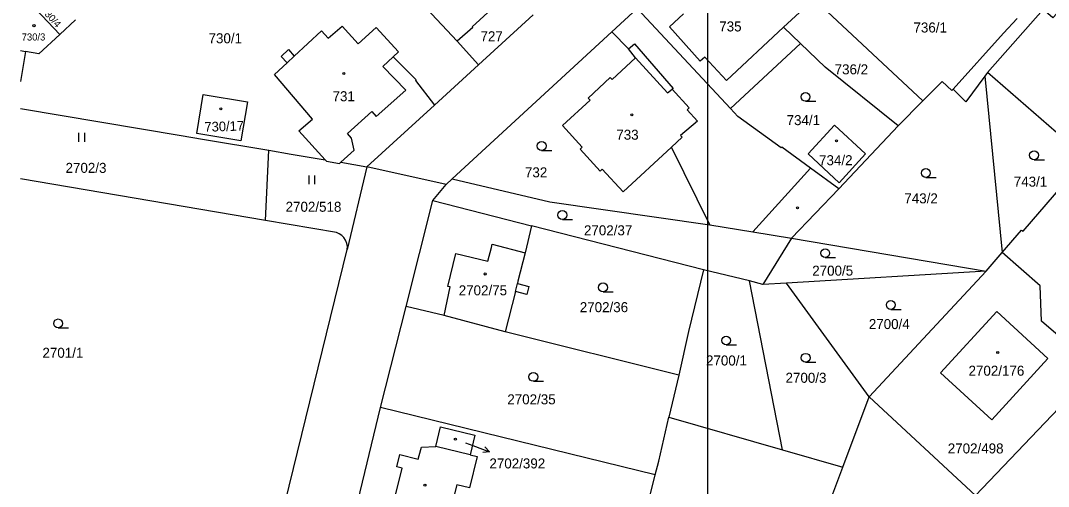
# Model space of a CAD drawing. Extents: x -496682 to -495907, y -1088575 to -1088018.
# Drawn here: x -496674.2 to -496499.5, y -1088360.6 to -1088281.4 of the extents above; entities that cross this region are included whole.
import ezdxf

# ---------------------------------------------------------------- set-up
doc = ezdxf.new("R2010")
doc.units = 0
for name, color, linetype in [('Hranice parcel', 7, 'Continuous'), ('Parcelní čísla', 7, 'Continuous'), ('Pop  PČ popisy', 7, 'Continuous'), ('Vnitřní kresba', 7, 'Continuous'), ('Vrstva 63', 7, 'Continuous'), ('Značky budov', 7, 'Continuous'), ('Značky kultur', 7, 'Continuous')]:
    doc.layers.add(name, color=color, linetype=linetype)

msp = doc.modelspace()

# ---------------------------------------------------------------- linework, layer by layer
at = {"layer": 'Hranice parcel'}
for p, q in [((-496548.9, -1088268.78), (-496520.79, -1088295.03)), ((-496667.54, -1088283.8), (-496671.59, -1088279.46)), ((-496569.37, -1088279.38), (-496573.69, -1088283.35)), ((-496553.5, -1088296.38), (-496569.37, -1088279.38)), ((-496664.84, -1088281.29), (-496667.54, -1088283.8)), ((-496596.36, -1088288.95), (-496587.04, -1088280.45)), ((-496573.69, -1088283.35), (-496600.82, -1088308.29)), ((-496674.2, -1088286.47), (-496673.36, -1088286.64)), ((-496673.36, -1088286.64), (-496674.2, -1088291.77)), ((-496599.99, -1088284.92), (-496596.36, -1088288.95)), ((-496541.63, -1088285.29), (-496553.5, -1088296.38)), ((-496603.81, -1088295.77), (-496596.36, -1088288.95)), ((-496509.82, -1088290.25), (-496510.27, -1088290.86)), ((-496510.27, -1088290.86), (-496507.31, -1088320.82)), ((-496493.08, -1088304.83), (-496509.82, -1088290.25)), ((-496524.98, -1088299.32), (-496520.79, -1088295.03)), ((-496615.31, -1088306.29), (-496603.81, -1088295.77)), ((-496535.11, -1088310.03), (-496524.98, -1088299.32)), ((-496632.58, -1088315.39), (-496631.97, -1088303.45)), ((-496615.31, -1088306.29), (-496618.66, -1088320.33)), ((-496601.85, -1088309.24), (-496615.31, -1088306.29)), ((-496632.58, -1088315.39), (-496674.2, -1088308.3)), ((-496604.09, -1088312.01), (-496601.85, -1088309.24)), ((-496600.82, -1088308.29), (-496601.85, -1088309.24)), ((-496543.15, -1088318.39), (-496535.11, -1088310.03)), ((-496608.66, -1088330.02), (-496604.09, -1088312.01)), ((-496604.09, -1088312.01), (-496587.31, -1088316.31)), ((-496620.51, -1088317.45), (-496632.58, -1088315.39)), ((-496558.12, -1088323.79), (-496587.31, -1088316.31)), ((-496543.15, -1088318.39), (-496547.99, -1088326.24)), ((-496543.15, -1088318.39), (-496510.05, -1088324)), ((-496629.19, -1088363.28), (-496618.66, -1088320.33)), ((-496510.05, -1088324), (-496507.31, -1088320.82)), ((-496550.3, -1088325.66), (-496558.12, -1088323.79)), ((-496510.05, -1088324), (-496543.99, -1088326.01)), ((-496529.95, -1088345.34), (-496510.05, -1088324)), ((-496544.65, -1088354.34), (-496550.3, -1088325.66)), ((-496547.99, -1088326.24), (-496550.3, -1088325.66)), ((-496543.99, -1088326.01), (-496547.99, -1088326.24)), ((-496529.95, -1088345.34), (-496543.99, -1088326.01)), ((-496613.01, -1088347.16), (-496608.66, -1088330.02)), ((-496562.31, -1088341.65), (-496591.79, -1088334.31)), ((-496562.31, -1088341.65), (-496563.97, -1088348.81)), ((-496534.41, -1088357.28), (-496529.95, -1088345.34)), ((-496511.87, -1088362.1), (-496529.95, -1088345.34)), ((-496617.24, -1088364.65), (-496613.01, -1088347.16)), ((-496566.3, -1088358.61), (-496613.01, -1088347.16)), ((-496563.97, -1088348.81), (-496544.65, -1088354.34)), ((-496597.79, -1088355.21), (-496603.63, -1088353.81)), ((-496544.65, -1088354.34), (-496534.41, -1088357.28)), ((-496549.47, -1088397.55), (-496534.41, -1088357.28)), ((-496570.63, -1088376), (-496566.3, -1088358.61))]:
    msp.add_line(p, q, dxfattribs=at)
for points in [[(-496541.63, -1088285.29), (-496544.48, -1088282.55), (-496541.11, -1088279.41), (-496545.16, -1088275.06), (-496544.67, -1088274.27), (-496549.3, -1088269.14), (-496548.9, -1088268.78)], [(-496613.46, -1088270.55), (-496609.56, -1088274.67), (-496599.99, -1088284.92)], [(-496471.64, -1088280.48), (-496481.44, -1088271.8), (-496490.1, -1088271.56), (-496498.71, -1088280.96), (-496500.38, -1088279.53), (-496509.82, -1088290.25)], [(-496590.86, -1088276.42), (-496597.43, -1088282.45), (-496597.33, -1088282.57), (-496599.99, -1088284.92)], [(-496515.68, -1088293.05), (-496507.09, -1088283.57), (-496504.76, -1088281.06)], [(-496622.44, -1088305.06), (-496626.89, -1088300.16), (-496624.57, -1088298.15), (-496631.04, -1088290.58), (-496628.89, -1088288.59), (-496629.91, -1088287.49), (-496628.67, -1088286.35), (-496627.66, -1088287.45), (-496623.04, -1088283.17), (-496621.92, -1088284.39), (-496619.54, -1088282.35), (-496616.81, -1088285.36), (-496613.73, -1088282.57), (-496609.93, -1088286.75), (-496610.83, -1088287.57), (-496606.92, -1088291.49), (-496607.06, -1088291.61), (-496603.81, -1088295.77)], [(-496667.54, -1088283.8), (-496671.07, -1088287.09), (-496673.36, -1088286.64)], [(-496557.01, -1088316.13), (-496563.54, -1088302.9), (-496571.78, -1088310.53), (-496575.32, -1088306.66), (-496575.68, -1088306.99), (-496579.09, -1088303.24), (-496578.73, -1088302.91), (-496582.06, -1088299.26), (-496577.39, -1088294.94), (-496577.72, -1088294.58), (-496573.95, -1088291.1), (-496573.62, -1088291.45), (-496569.64, -1088287.77), (-496570.83, -1088286.2), (-496573.69, -1088283.35)], [(-496524.98, -1088299.32), (-496537.43, -1088289.33), (-496541.63, -1088285.29)], [(-496520.79, -1088295.03), (-496517.54, -1088291.78), (-496515.9, -1088293.3), (-496515.68, -1088293.05)], [(-496510.27, -1088290.86), (-496513.48, -1088295.21), (-496515.68, -1088293.05)], [(-496636.73, -1088301.87), (-496644.24, -1088300.6), (-496643.15, -1088293.97), (-496635.64, -1088295.22), (-496636.73, -1088301.87)], [(-496674.2, -1088296.34), (-496646.9, -1088300.94), (-496643.26, -1088301.55), (-496631.97, -1088303.45)], [(-496535.11, -1088310.03), (-496539.93, -1088306.49), (-496544.78, -1088302.93), (-496544.87, -1088303.05), (-496552.24, -1088297.73), (-496553.5, -1088296.38)], [(-496535.04, -1088308.98), (-496540.33, -1088304.08), (-496535.81, -1088299.21), (-496530.53, -1088304.07), (-496535.04, -1088308.98)], [(-496631.97, -1088303.45), (-496628.18, -1088304.09), (-496622.44, -1088305.06)], [(-496622.44, -1088305.06), (-496622.2, -1088305.33), (-496619.97, -1088305.68), (-496619.76, -1088305.49), (-496615.31, -1088306.29)], [(-496507.31, -1088320.82), (-496504.02, -1088317), (-496503.76, -1088317.22), (-496493.08, -1088304.83)], [(-496600.82, -1088308.29), (-496584.23, -1088312.23), (-496557.01, -1088316.13)], [(-496587.31, -1088316.31), (-496588.44, -1088320.85), (-496589.65, -1088325.71), (-496589.74, -1088326.09), (-496587.78, -1088326.58), (-496588.11, -1088327.93), (-496590.08, -1088327.44), (-496591.79, -1088334.31)], [(-496557.01, -1088316.13), (-496549.73, -1088317.32), (-496543.15, -1088318.39)], [(-496618.66, -1088320.33), (-496618.64, -1088319.82), (-496618.71, -1088319.31), (-496618.89, -1088318.83), (-496618.96, -1088318.7), (-496619.24, -1088318.28), (-496619.61, -1088317.92), (-496620.04, -1088317.64), (-496620.51, -1088317.45)], [(-496495.35, -1088337), (-496500.62, -1088332.48), (-496500.87, -1088326.47), (-496507.31, -1088320.82)], [(-496558.12, -1088323.79), (-496560.67, -1088334.24), (-496562.31, -1088341.65)], [(-496591.79, -1088334.31), (-496602.19, -1088331.54), (-496608.66, -1088330.02)], [(-496508.23, -1088330.82), (-496517.83, -1088341.24), (-496509.1, -1088349.28), (-496499.58, -1088338.82), (-496508.23, -1088330.82)], [(-496495.35, -1088337), (-496495.31, -1088344.8), (-496511.87, -1088362.1)], [(-496566.3, -1088358.61), (-496565.71, -1088356.26), (-496563.97, -1088348.81)], [(-496603.63, -1088353.81), (-496602.83, -1088350.47), (-496597, -1088351.88), (-496597.79, -1088355.21)], [(-496611.47, -1088366.13), (-496609.31, -1088357.47), (-496610.23, -1088357.24), (-496609.71, -1088355.17), (-496606.59, -1088355.94), (-496606.43, -1088355.33), (-496606.05, -1088353.9), (-496603.63, -1088353.81)], [(-496597.79, -1088355.21), (-496596.58, -1088355.5), (-496597.86, -1088360.83), (-496600.06, -1088360.3), (-496602.12, -1088368.5)]]:
    msp.add_lwpolyline(points, dxfattribs=at)
at = {"layer": 'Pop  PČ popisy'}
for p, q in [((-496598.58, -1088353.17), (-496597.3, -1088353.64)), ((-496597.3, -1088353.64), (-496594.48, -1088354.67)), ((-496594.48, -1088354.67), (-496595.59, -1088354.79)), ((-496594.48, -1088354.67), (-496595.25, -1088353.85))]:
    msp.add_line(p, q, dxfattribs=at)
at = {"layer": 'Vnitřní kresba'}
for p, q in [((-496563.86, -1088282.47), (-496561.48, -1088280.26)), ((-496558.66, -1088288.31), (-496563.86, -1088282.47)), ((-496544.48, -1088282.55), (-496554.18, -1088291.59)), ((-496570.83, -1088286.2), (-496569.84, -1088285.35)), ((-496569.84, -1088285.35), (-496563.27, -1088292.94)), ((-496627.66, -1088287.45), (-496628.89, -1088288.59)), ((-496612.62, -1088289.19), (-496610.83, -1088287.57)), ((-496569.64, -1088287.77), (-496564.22, -1088293.68)), ((-496557.88, -1088287.62), (-496558.66, -1088288.31)), ((-496554.18, -1088291.59), (-496557.88, -1088287.62)), ((-496608.71, -1088293.21), (-496612.62, -1088289.19)), ((-496613.73, -1088297.7), (-496608.71, -1088293.21)), ((-496564.22, -1088293.68), (-496563.42, -1088293.06)), ((-496563.27, -1088292.94), (-496563.42, -1088293.06)), ((-496563.42, -1088293.06), (-496560.51, -1088296.25)), ((-496618.63, -1088300.61), (-496614.51, -1088296.84)), ((-496614.51, -1088296.84), (-496613.73, -1088297.7)), ((-496560.51, -1088296.25), (-496560.88, -1088296.59)), ((-496560.88, -1088296.59), (-496559.1, -1088298.52)), ((-496559.1, -1088298.52), (-496561.98, -1088300.95)), ((-496617.93, -1088301.38), (-496618.63, -1088300.61)), ((-496617.51, -1088303.44), (-496617.93, -1088301.38)), ((-496561.73, -1088301.22), (-496563.54, -1088302.9)), ((-496561.98, -1088300.95), (-496561.73, -1088301.22)), ((-496619.76, -1088305.49), (-496617.51, -1088303.44)), ((-496539.93, -1088306.49), (-496549.73, -1088317.32)), ((-496594.15, -1088319.98), (-496594.01, -1088319.42)), ((-496594.01, -1088319.42), (-496588.44, -1088320.85)), ((-496601.58, -1088326.57), (-496600.18, -1088320.97)), ((-496600.18, -1088320.97), (-496594.74, -1088322.29)), ((-496594.74, -1088322.29), (-496594.15, -1088319.98)), ((-496602.19, -1088331.54), (-496601.19, -1088326.65)), ((-496601.19, -1088326.65), (-496601.58, -1088326.57)), ((-496590.08, -1088327.44), (-496589.74, -1088326.09))]:
    msp.add_line(p, q, dxfattribs=at)
at = {"layer": 'Vrstva 63'}
msp.add_lwpolyline([(-496137.35, -1088164.24), (-496137.35, -1088461.24), (-496557.35, -1088461.24), (-496557.35, -1088164.24)], close=True, dxfattribs=at)
at = {"layer": 'Značky budov'}
for centre in [(-496671.92, -1088282.28), (-496619.24, -1088290.39), (-496640.16, -1088296.42), (-496570.29, -1088297.44), (-496535.47, -1088301.84), (-496542.11, -1088313.23), (-496595.2, -1088324.47), (-496508.08, -1088337.83), (-496600.28, -1088352.55), (-496605.45, -1088360.35)]:
    msp.add_circle(centre, 0.175, dxfattribs=at)
at = {"layer": 'Značky kultur'}
for p, q in [((-496540.75, -1088295.13), (-496539, -1088295.13)), ((-496664.27, -1088301.99), (-496664.27, -1088300.49)), ((-496663.27, -1088301.99), (-496663.27, -1088300.49)), ((-496585.61, -1088303.47), (-496583.86, -1088303.47)), ((-496501.9, -1088305.05), (-496500.15, -1088305.05)), ((-496625.15, -1088309.23), (-496625.15, -1088307.73)), ((-496624.15, -1088309.23), (-496624.15, -1088307.73)), ((-496520.3, -1088308.07), (-496518.55, -1088308.07)), ((-496582.09, -1088315.2), (-496580.34, -1088315.2)), ((-496537.4, -1088321.69), (-496535.65, -1088321.69)), ((-496575.18, -1088327.5), (-496573.43, -1088327.5)), ((-496526.26, -1088330.48), (-496524.51, -1088330.48)), ((-496667.82, -1088333.62), (-496666.07, -1088333.62)), ((-496554.25, -1088336.52), (-496552.5, -1088336.52)), ((-496540.73, -1088339.46), (-496538.98, -1088339.46)), ((-496587.02, -1088342.71), (-496585.27, -1088342.71))]:
    msp.add_line(p, q, dxfattribs=at)
for centre in [(-496540.75, -1088294.38), (-496585.61, -1088302.72), (-496501.9, -1088304.3), (-496520.3, -1088307.32), (-496582.09, -1088314.45), (-496537.4, -1088320.94), (-496575.18, -1088326.75), (-496526.26, -1088329.73), (-496667.82, -1088332.87), (-496554.25, -1088335.77), (-496540.73, -1088338.71), (-496587.02, -1088341.96)]:
    msp.add_circle(centre, 0.75, dxfattribs=at)

# ---------------------------------------------------------------- texts
at = {"layer": 'Parcelní čísla'}
for s, height, rotation, p in [('730/4', 1.2, 312, (-496670.79, -1088279.72)), ('730/17', 1.643, 2, (-496642.91, -1088300.32))]:
    msp.add_text(s, height=height, rotation=rotation, dxfattribs=at).set_placement(p)
for s, height, p in [('735', 1.7, (-496555.42, -1088283.26)), ('736/1', 1.7, (-496522.4, -1088283.44)), ('730/3', 1.2, (-496674.01, -1088284.8)), ('730/1', 1.7, (-496642.24, -1088285.27)), ('727', 1.7, (-496596.01, -1088284.93)), ('736/2', 1.7, (-496535.8, -1088290.55)), ('731', 1.7, (-496621.16, -1088295.12)), ('734/1', 1.7, (-496543.97, -1088299.18)), ('733', 1.7, (-496572.92, -1088301.66)), ('2702/3', 1.7, (-496666.55, -1088307.29)), ('734/2', 1.7, (-496538.45, -1088305.99)), ('732', 1.7, (-496588.45, -1088308.05)), ('743/1', 1.7, (-496505.35, -1088309.63)), ('743/2', 1.7, (-496523.95, -1088312.47)), ('2702/518', 1.7, (-496629.14, -1088313.9)), ('2702/37', 1.7, (-496578.42, -1088317.9)), ('2700/5', 1.7, (-496539.61, -1088324.76)), ('2702/75', 1.7, (-496599.71, -1088328.1)), ('2702/36', 1.7, (-496579.13, -1088330.96)), ('2700/4', 1.7, (-496529.99, -1088333.83)), ('2701/1', 1.7, (-496670.48, -1088338.71)), ('2700/1', 1.7, (-496557.67, -1088340.02)), ('2702/176', 1.7, (-496513.04, -1088341.76)), ('2700/3', 1.7, (-496544.15, -1088342.96)), ('2702/35', 1.7, (-496591.45, -1088346.62)), ('2702/498', 1.7, (-496516.57, -1088354.96)), ('2702/392', 1.7, (-496594.49, -1088357.51))]:
    msp.add_text(s, height=height, dxfattribs=at).set_placement(p)

doc.saveas('drawing.dxf')
